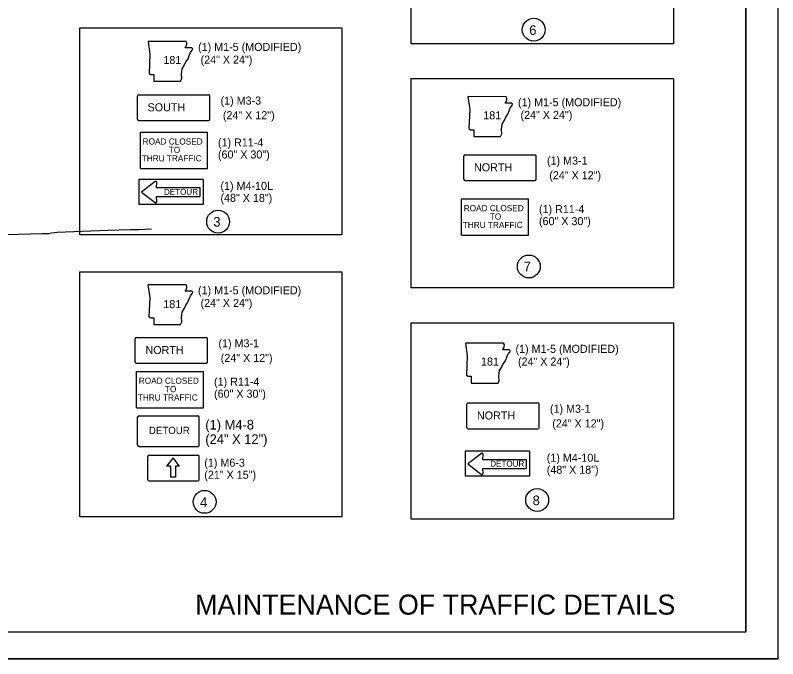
# Model space of a CAD drawing. Extents: x 9792 to 14027, y 9583 to 10649.
# Drawn here: x 10889 to 11459, y 9583 to 10064 of the extents above; entities that cross this region are included whole.
import ezdxf

# ---------------------------------------------------------------- set-up
doc = ezdxf.new("R2010")
doc.units = 0
for name, color, linetype in [('Default', 7, 'Continuous'), ('R_Border', 7, 'Continuous'), ('R_Border Notes', 7, 'Continuous'), ('R_MOT', 7, 'Continuous'), ('R_No Plot', 7, 'Continuous'), ('R_Striping', 7, 'Continuous')]:
    doc.layers.add(name, color=color, linetype=linetype)

msp = doc.modelspace()

# ---------------------------------------------------------------- linework, layer by layer
at = {"layer": 'Default'}
msp.add_lwpolyline([(10991.02, 9903.67), (10981.35, 9903.27), (10975.17, 9903.16), (10958.03, 9902.72), (10951.9, 9902.38), (10920.5, 9901.06), (10916.21, 9900.74), (10914.15, 9900.26), (10909.31, 9900.11), (10882.9, 9899.31), (10871.18, 9898.84), (10853.18, 9895.05), (10832.49, 9891.39)], dxfattribs=at)
at = {"layer": 'R_Border'}
for q in [(11435.16, 10629.85), (9854.26, 9602.55)]:
    msp.add_line((11435.16, 9602.55), q, dxfattribs=at)
at = {"layer": 'R_Border Notes'}
for p, q in [((10980.34, 9985.83), (10980.34, 10003.11)), ((10981.3, 10004.07), (11033.48, 10004.07)), ((11034.44, 9985.83), (11034.44, 10003.12)), ((10981.3, 9984.88), (11033.48, 9984.87)), ((10982.6, 9976.04), (11032.79, 9976.04)), ((10982.6, 9948.9), (10982.6, 9976.04)), ((11032.79, 9948.9), (11032.79, 9976.04)), ((11224.29, 9940.98), (11224.29, 9958.26)), ((11225.25, 9959.22), (11277.43, 9959.22)), ((11278.39, 9940.98), (11278.39, 9958.26)), ((10982.6, 9948.9), (11032.79, 9948.9)), ((11225.25, 9940.02), (11277.43, 9940.02)), ((11222.52, 9926.25), (11272.71, 9926.25)), ((11222.52, 9899.11), (11222.52, 9926.25)), ((11272.71, 9899.11), (11272.71, 9926.25)), ((11222.52, 9899.11), (11272.71, 9899.11)), ((10978.79, 9804.45), (10978.79, 9821.73)), ((10979.75, 9822.69), (11031.92, 9822.69)), ((11032.88, 9804.45), (11032.88, 9821.73)), ((10979.75, 9803.49), (11031.92, 9803.49)), ((10979.7, 9797.28), (11029.89, 9797.28)), ((10979.7, 9770.13), (10979.7, 9797.28)), ((11029.89, 9770.13), (11029.89, 9797.28)), ((11226.51, 9755.53), (11226.51, 9772.81)), ((11227.47, 9773.77), (11279.64, 9773.77)), ((11280.6, 9755.53), (11280.6, 9772.81)), ((10979.7, 9770.13), (11029.89, 9770.13)), ((11227.47, 9754.57), (11279.64, 9754.57)), ((10988.22, 9716.44), (10988.22, 9733.73)), ((10989.18, 9734.69), (11025.67, 9734.69)), ((11007.02, 9732.72), (11002.22, 9726.49)), ((11011.82, 9726.49), (11007.02, 9732.72)), ((11026.63, 9716.44), (11026.63, 9733.73)), ((11005.22, 9726.49), (11002.22, 9726.49)), ((11005.22, 9726.49), (11005.22, 9722.68)), ((11005.22, 9722.68), (11005.22, 9718.31)), ((11011.82, 9726.49), (11008.82, 9726.49)), ((11008.82, 9726.49), (11008.82, 9722.68)), ((11008.82, 9722.68), (11008.82, 9718.31)), ((10989.18, 9715.48), (11025.67, 9715.48)), ((11008.82, 9718.31), (11005.22, 9718.31))]:
    msp.add_line(p, q, dxfattribs=at)
for points in [[(11185.08, 10233.35), (11380.91, 10233.35), (11380.91, 10042.2), (11185.08, 10042.2)], [(10937.26, 10054.23), (11133.09, 10054.23), (11133.09, 9899.32), (10937.26, 9899.32)], [(10988.32, 10044), (10989.73, 10034.49), (10989.08, 10020.08), (10990.35, 10019.29), (10992.72, 10019.29), (10992.72, 10014.22), (11012.67, 10014.2), (11013.63, 10016.26), (11013.31, 10019.58), (11013.79, 10023.39), (11015.53, 10026.39), (11016.65, 10028.61), (11018.23, 10030.98), (11019.19, 10033.51), (11019.98, 10035.57), (11021.41, 10037.31), (11021.72, 10038.42), (11021.09, 10039.21), (11016.18, 10039.22), (11017.29, 10041.43), (11017.45, 10042.86), (11016.8, 10043.95)], [(11185.08, 10016.35), (11380.91, 10016.35), (11380.91, 9859.89), (11185.08, 9859.89)], [(11227.41, 10002.69), (11228.82, 9993.18), (11228.17, 9978.77), (11229.44, 9977.98), (11231.81, 9977.98), (11231.81, 9972.91), (11251.76, 9972.89), (11252.71, 9974.95), (11252.4, 9978.27), (11252.88, 9982.08), (11254.62, 9985.08), (11255.73, 9987.3), (11257.32, 9989.67), (11258.27, 9992.2), (11259.07, 9994.26), (11260.5, 9996), (11260.81, 9997.11), (11260.18, 9997.9), (11255.27, 9997.91), (11256.38, 10000.12), (11256.54, 10001.55), (11255.88, 10002.64)], [(10937.26, 9871.71), (11133.09, 9871.71), (11133.09, 9688.75), (10937.26, 9688.75)], [(10988.29, 9862.14), (10989.7, 9852.64), (10989.05, 9838.23), (10990.32, 9837.44), (10992.69, 9837.44), (10992.69, 9832.37), (11012.64, 9832.35), (11013.6, 9834.41), (11013.28, 9837.73), (11013.76, 9841.53), (11015.51, 9844.54), (11016.62, 9846.75), (11018.2, 9849.13), (11019.16, 9851.66), (11019.95, 9853.72), (11021.38, 9855.46), (11021.7, 9856.56), (11021.06, 9857.36), (11016.15, 9857.36), (11017.26, 9859.58), (11017.42, 9861.01), (11016.77, 9862.1)], [(11185.08, 9833.73), (11380.91, 9833.73), (11380.91, 9687.04), (11185.08, 9687.04)], [(11225.51, 9818.38), (11226.93, 9808.88), (11226.28, 9794.47), (11227.55, 9793.68), (11229.92, 9793.68), (11229.92, 9788.61), (11249.87, 9788.59), (11250.82, 9790.65), (11250.5, 9793.97), (11250.98, 9797.77), (11252.73, 9800.78), (11253.84, 9803), (11255.43, 9805.37), (11256.38, 9807.9), (11257.17, 9809.96), (11258.6, 9811.7), (11258.92, 9812.81), (11258.28, 9813.6), (11253.37, 9813.6), (11254.48, 9815.82), (11254.65, 9817.25), (11253.99, 9818.34)]]:
    msp.add_lwpolyline(points, close=True, dxfattribs=at)
for centre in [(11276.59, 10052.67), (11040.71, 9909.23), (11272.88, 9875.78), (11279.13, 9701.25), (11030.59, 9699.87)]:
    msp.add_circle(centre, 8.55, dxfattribs=at)
for centre, start, end in [((10981.3, 10003.11), 90, 180), ((11033.48, 10003.11), 0, 90), ((10981.3, 9985.83), 180, 270), ((11033.48, 9985.83), 270, 0), ((11225.25, 9958.26), 90, 180), ((11277.43, 9958.26), 0, 90), ((11225.25, 9940.98), 180, 270), ((11277.43, 9940.98), 270, 0), ((10979.75, 9821.73), 90, 180), ((11031.92, 9821.73), 0, 90), ((10979.75, 9804.45), 180, 270), ((11031.92, 9804.45), 270, 0), ((11227.47, 9772.81), 90, 180), ((11279.64, 9772.81), 0, 90), ((11227.47, 9755.53), 180, 270), ((11279.64, 9755.53), 270, 0), ((10989.18, 9733.73), 90, 180), ((11025.67, 9733.73), 0, 90), ((10989.18, 9716.44), 180, 270), ((11025.67, 9716.44), 270, 0)]:
    msp.add_arc(centre, 0.96, start, end, dxfattribs=at)
at = {"layer": 'R_MOT'}
for p, q in [((11029.66, 9940.86), (10981.58, 9940.86)), ((10981.58, 9940.86), (10981.58, 9922.17)), ((10993.62, 9939.26), (10983.37, 9931.36)), ((10994.68, 9938.68), (10994.36, 9934.67)), ((11029.66, 9940.86), (11029.66, 9922.17)), ((10994.36, 9934.67), (11027.16, 9934.67)), ((11027.16, 9934.67), (11027.16, 9928.06)), ((10983.37, 9931.36), (10993.62, 9923.47)), ((10994.35, 9928.06), (11027.16, 9928.06)), ((10994.35, 9928.06), (10994.67, 9924.05)), ((11029.66, 9922.17), (10981.58, 9922.17)), ((10980.55, 9742.3), (10980.55, 9763.04)), ((10981.7, 9764.19), (11025.48, 9764.19)), ((11026.63, 9742.3), (11026.63, 9763.04)), ((10981.7, 9741.15), (11025.48, 9741.15)), ((11273.52, 9737.69), (11225.44, 9737.69)), ((11225.44, 9737.69), (11225.44, 9719.01)), ((11237.48, 9736.09), (11227.23, 9728.2)), ((11238.54, 9735.52), (11238.21, 9731.5)), ((11273.52, 9737.69), (11273.52, 9719.01)), ((11227.23, 9728.2), (11237.47, 9720.31)), ((11238.21, 9731.5), (11271.02, 9731.5)), ((11271.02, 9731.5), (11271.02, 9724.9)), ((11238.21, 9724.9), (11271.02, 9724.9)), ((11238.21, 9724.9), (11238.53, 9720.88)), ((11273.52, 9719.01), (11225.44, 9719.01))]:
    msp.add_line(p, q, dxfattribs=at)
for centre, radius, start, end in [((10994.02, 9938.73), 0.66, 355.4261, 127.6147), ((10994.02, 9924), 0.66, 232.3888, 4.5739), ((10981.7, 9763.04), 1.15, 90, 180), ((11025.48, 9763.04), 1.15, 0, 90), ((10981.7, 9742.3), 1.15, 180, 270), ((11025.48, 9742.3), 1.15, 270, 0), ((11237.88, 9735.57), 0.66, 355.4261, 127.6147), ((11237.88, 9720.83), 0.66, 232.3888, 4.5739)]:
    msp.add_arc(centre, radius, start, end, dxfattribs=at)
at = {"layer": 'R_No Plot'}
msp.add_line((9792.26, 9582.66), (11458.93, 9582.66), dxfattribs=at)
for points in [[(9792.23, 10649.32), (11458.93, 10649.32), (11458.93, 9582.63), (9792.23, 9582.63)], [(11023.86, 10629.85), (11023.86, 10580.45), (11202.52, 10580.45), (11202.52, 10565.85), (11318.52, 10565.85), (11318.52, 10444.19), (11435.16, 10444.19), (11435.16, 9602.55), (9854.26, 9602.55), (9854.26, 10629.85)]]:
    msp.add_lwpolyline(points, close=True, dxfattribs=at)

# ---------------------------------------------------------------- texts
at = {"layer": 'R_Border Notes'}
for s, height, p in [('6', 7.2, (11273.23, 10048.82)), ('(1) M1-5 (MODIFIED)', 6, (11025.74, 10036.83)), ('181', 6, (10999.81, 10027.07)), ('(24" X 24")', 6.0005, (11027.6, 10027.36)), ('(1) M3-3', 6, (11042.53, 9996.75)), ('(1) M1-5 (MODIFIED)', 6, (11264.83, 9995.52)), ('  SOUTH', 6, (10983.53, 9991.73)), ('(24" X 12")', 6, (11044.25, 9985.81)), ('181', 6, (11238.89, 9985.76)), ('(24" X 24")', 6.0005, (11266.68, 9986.05)), ('ROAD CLOSED', 4.604, (10984.34, 9966.88)), ('(1) R11-4', 6, (11040.58, 9965.45)), ('TO', 4.604, (11003.84, 9960.59)), ('(60" X 30")', 6, (11040.58, 9956.45)), ('THRU TRAFFIC', 4.604, (10983.61, 9954.31)), ('(1) M3-1', 6, (11286.48, 9951.9)), ('  NORTH', 6, (11227.48, 9946.88)), ('(24" X 12")', 6, (11288.2, 9940.95)), ('ROAD CLOSED', 4.604, (11224.26, 9917.09)), ('(1) R11-4', 6, (11280.5, 9915.66)), ('TO', 4.604, (11243.76, 9910.8)), ('3', 7.2, (11037.12, 9905.56)), ('THRU TRAFFIC', 4.604, (11223.53, 9904.52)), ('(60" X 30")', 6, (11280.5, 9906.66)), ('7', 7.2, (11269.06, 9872.14)), ('(1) M1-5 (MODIFIED)', 6, (11025.71, 9854.97)), ('181', 6, (10999.78, 9844.64)), ('(24" X 24")', 6.0005, (11027.57, 9845.51)), ('(1) M3-1', 6, (11040.97, 9815.36)), ('  NORTH', 6, (10981.97, 9810.35)), ('(1) M1-5 (MODIFIED)', 6, (11262.93, 9811.22)), ('(24" X 12")', 6, (11042.7, 9804.42)), ('181', 6, (11237.16, 9801.73)), ('(24" X 24")', 6.0005, (11264.79, 9801.75)), ('ROAD CLOSED', 4.604, (10981.44, 9788.11)), ('(1) R11-4', 6, (11037.68, 9786.69)), ('TO', 4.604, (11000.95, 9781.83)), ('(60" X 30")', 6, (11037.68, 9777.69)), ('THRU TRAFFIC', 4.604, (10980.71, 9775.55)), ('(1) M3-1', 6, (11288.69, 9766.44)), ('  NORTH', 6, (11229.69, 9761.43)), ('(24" X 12")', 6, (11290.42, 9755.5)), ('(1) M6-3', 6.001, (11030.38, 9726.14)), ('(21" X 15")', 6.0007, (11030.38, 9717.14)), ('8', 7.2, (11275.77, 9697.4)), ('4', 7.2, (11027.23, 9696.02))]:
    msp.add_text(s, height=height, dxfattribs=at).set_placement(p)
at = {"layer": 'R_MOT'}
for s, height, p in [('(1) M4-10L', 6, (11042.45, 9933.03)), ('DETOUR', 4.511, (11000.21, 9929.26)), ('(48" X 18")', 6, (11042.45, 9924.03)), ('(1) M4-10L', 6, (11286.31, 9729.87)), ('DETOUR', 4.511, (11244.07, 9726.1)), ('(48" X 18")', 6, (11286.31, 9720.87))]:
    msp.add_text(s, height=height, rotation=360, dxfattribs=at).set_placement(p)
for s, height, p in [('(1) M4-8', 7.2, (11031.13, 9753.94)), ('DETOUR', 5.413, (10988.97, 9750.59)), ('(24" X 12")', 7.2, (11031.13, 9743.14))]:
    msp.add_text(s, height=height, dxfattribs=at).set_placement(p)
at = {"layer": 'R_Striping'}
msp.add_text('MAINTENANCE OF TRAFFIC DETAILS', height=15, dxfattribs=at).set_placement((11023.52, 9615.6))

doc.saveas('drawing.dxf')
